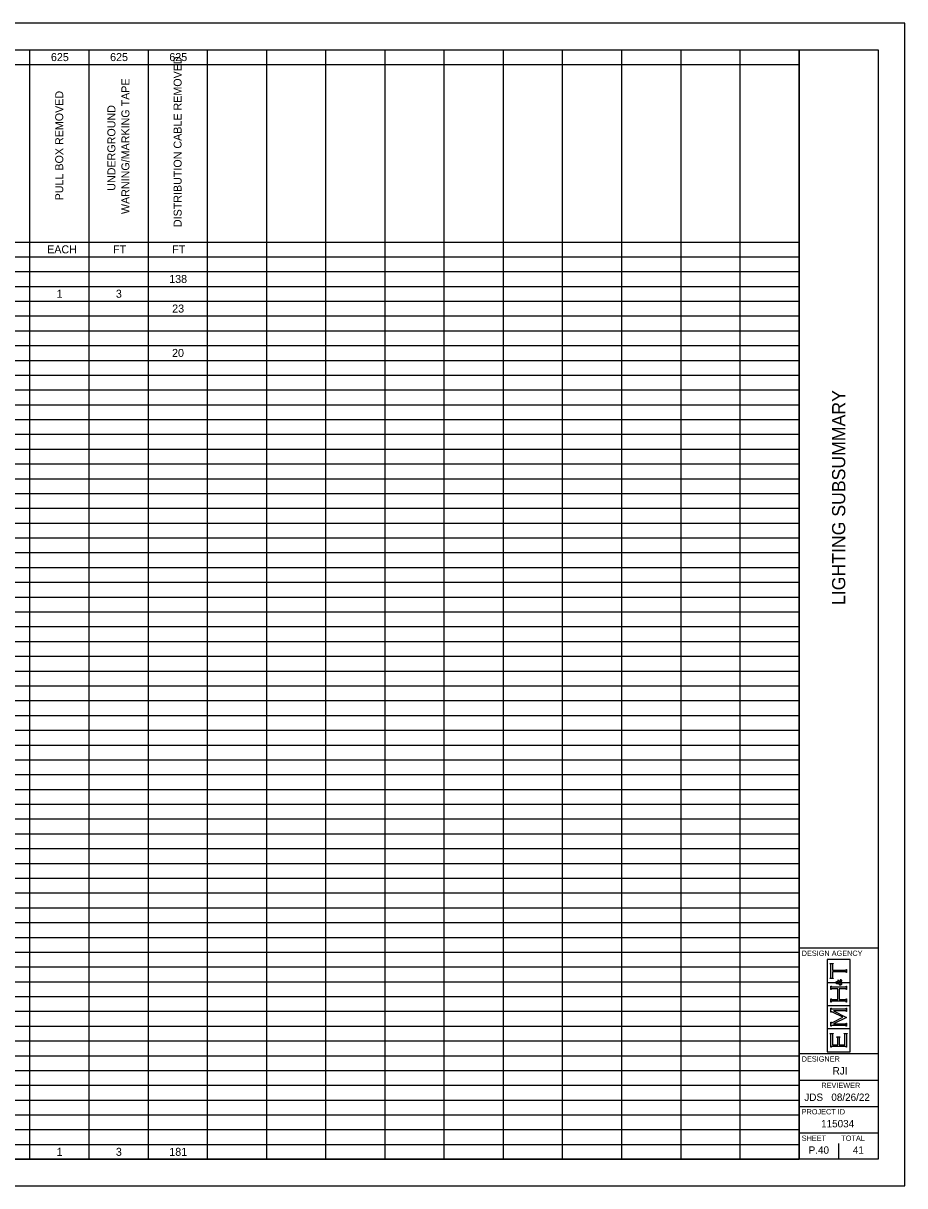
# Model space of a CAD drawing. Extents: x 0 to 34, y 0 to 22.
# Drawn here: x 17.32 to 34, y 0 to 22 of the extents above; entities that cross this region are included whole.
import ezdxf

# ---------------------------------------------------------------- set-up
doc = ezdxf.new("R2010")
doc.units = 0
for name, color, linetype in [('SH_Border', 7, 'Continuous'), ('SH_Cut_Line', 7, 'Continuous'), ('SH_Data', 7, 'Continuous'), ('SH_Text', 7, 'Continuous')]:
    doc.layers.add(name, color=color, linetype=linetype)

msp = doc.modelspace()

# ---------------------------------------------------------------- linework, layer by layer
at = {"layer": 'SH_Border'}
for p, q in [((32, 0.5), (32, 21.5)), ((32, 4.5), (33.5, 4.5)), ((32, 2.5), (33.5, 2.5)), ((32, 2), (33.5, 2)), ((32, 1.5), (33.5, 1.5)), ((32, 1), (33.5, 1))]:
    msp.add_line(p, q, dxfattribs=at)
msp.add_lwpolyline([(1.5, 21.5), (33.5, 21.5), (33.5, 0.5), (1.5, 0.5)], close=True, dxfattribs=at)
at = {"layer": 'SH_Cut_Line'}
msp.add_lwpolyline([(0, 0), (34, 0), (34, 22), (0, 22)], close=True, dxfattribs=at)
at = {"layer": 'SH_Data'}
for p, q in [((32.966, 4.28), (32.534, 4.28)), ((32.534, 4.28), (32.534, 3.848)), ((32.588, 4.199), (32.588, 4.206)), ((32.588, 4.206), (32.644, 4.206)), ((32.594, 4.198), (32.588, 4.199)), ((32.598, 4.196), (32.594, 4.198)), ((32.599, 4.194), (32.598, 4.196)), ((32.601, 4.191), (32.599, 4.194)), ((32.602, 4.187), (32.601, 4.191)), ((32.602, 4.181), (32.602, 4.187)), ((32.602, 3.947), (32.602, 4.181)), ((32.632, 4.191), (32.631, 4.187)), ((32.631, 4.187), (32.631, 4.181)), ((32.631, 4.181), (32.631, 4.081)), ((32.633, 4.194), (32.632, 4.191)), ((32.635, 4.196), (32.633, 4.194)), ((32.639, 4.198), (32.635, 4.196)), ((32.644, 4.199), (32.639, 4.198)), ((32.644, 4.206), (32.644, 4.199)), ((32.966, 3.848), (32.966, 4.28)), ((32.631, 4.081), (32.872, 4.081)), ((32.872, 4.047), (32.631, 4.047)), ((32.631, 4.047), (32.631, 3.947)), ((32.872, 4.081), (32.878, 4.081)), ((32.878, 4.047), (32.872, 4.047)), ((32.878, 4.081), (32.882, 4.082)), ((32.883, 4.046), (32.878, 4.047)), ((32.882, 4.082), (32.885, 4.084)), ((32.885, 4.044), (32.883, 4.046)), ((32.885, 4.084), (32.887, 4.085)), ((32.888, 4.042), (32.885, 4.044)), ((32.887, 4.085), (32.889, 4.089)), ((32.889, 4.039), (32.888, 4.042)), ((32.889, 4.089), (32.891, 4.095)), ((32.891, 4.033), (32.889, 4.039)), ((32.891, 4.095), (32.898, 4.095)), ((32.898, 4.033), (32.891, 4.033)), ((32.898, 4.095), (32.898, 4.033)), ((32.534, 3.848), (32.693, 3.848)), ((32.693, 3.842), (32.534, 3.842)), ((32.534, 3.842), (32.534, 3.41)), ((32.588, 3.928), (32.594, 3.93)), ((32.588, 3.921), (32.588, 3.928)), ((32.644, 3.921), (32.588, 3.921)), ((32.594, 3.93), (32.598, 3.932)), ((32.598, 3.932), (32.599, 3.934)), ((32.599, 3.934), (32.601, 3.937)), ((32.601, 3.937), (32.602, 3.941)), ((32.602, 3.941), (32.602, 3.947)), ((32.602, 3.714), (32.602, 3.776)), ((32.602, 3.776), (32.609, 3.776)), ((32.609, 3.776), (32.611, 3.77)), ((32.611, 3.77), (32.612, 3.766)), ((32.612, 3.766), (32.615, 3.765)), ((32.615, 3.765), (32.617, 3.763)), ((32.617, 3.763), (32.622, 3.762)), ((32.622, 3.762), (32.628, 3.762)), ((32.628, 3.762), (32.872, 3.762)), ((32.631, 3.947), (32.631, 3.941)), ((32.631, 3.941), (32.632, 3.937)), ((32.632, 3.937), (32.633, 3.934)), ((32.633, 3.934), (32.635, 3.932)), ((32.635, 3.932), (32.639, 3.93)), ((32.639, 3.93), (32.644, 3.928)), ((32.644, 3.928), (32.644, 3.921)), ((32.693, 3.848), (32.693, 3.842)), ((32.701, 3.852), (32.703, 3.857)), ((32.701, 3.846), (32.701, 3.852)), ((32.701, 3.84), (32.701, 3.846)), ((32.703, 3.835), (32.701, 3.84)), ((32.703, 3.857), (32.706, 3.861)), ((32.706, 3.83), (32.703, 3.835)), ((32.706, 3.861), (32.71, 3.864)), ((32.707, 3.852), (32.706, 3.849)), ((32.706, 3.849), (32.706, 3.846)), ((32.706, 3.846), (32.706, 3.842)), ((32.706, 3.842), (32.708, 3.839)), ((32.71, 3.824), (32.706, 3.83)), ((32.71, 3.854), (32.707, 3.852)), ((32.708, 3.839), (32.711, 3.837)), ((32.71, 3.864), (32.714, 3.866)), ((32.712, 3.856), (32.71, 3.854)), ((32.717, 3.821), (32.71, 3.824)), ((32.711, 3.837), (32.714, 3.835)), ((32.715, 3.857), (32.712, 3.856)), ((32.714, 3.866), (32.719, 3.866)), ((32.714, 3.835), (32.716, 3.834)), ((32.718, 3.857), (32.715, 3.857)), ((32.716, 3.834), (32.719, 3.834)), ((32.725, 3.821), (32.717, 3.821)), ((32.723, 3.857), (32.718, 3.857)), ((32.719, 3.866), (32.724, 3.866)), ((32.719, 3.834), (32.722, 3.834)), ((32.722, 3.834), (32.724, 3.834)), ((32.727, 3.856), (32.723, 3.857)), ((32.724, 3.866), (32.728, 3.864)), ((32.724, 3.834), (32.727, 3.835)), ((32.728, 3.821), (32.725, 3.821)), ((32.73, 3.853), (32.727, 3.856)), ((32.727, 3.835), (32.73, 3.836)), ((32.728, 3.864), (32.732, 3.861)), ((32.731, 3.822), (32.728, 3.821)), ((32.734, 3.85), (32.73, 3.853)), ((32.73, 3.836), (32.734, 3.837)), ((32.734, 3.822), (32.731, 3.822)), ((32.732, 3.861), (32.736, 3.857)), ((32.737, 3.845), (32.734, 3.85)), ((32.734, 3.837), (32.74, 3.839)), ((32.737, 3.823), (32.734, 3.822)), ((32.736, 3.857), (32.74, 3.851)), ((32.74, 3.839), (32.737, 3.845)), ((32.741, 3.825), (32.737, 3.823)), ((32.738, 3.867), (32.738, 3.898)), ((32.738, 3.898), (32.741, 3.898)), ((32.741, 3.867), (32.738, 3.867)), ((32.74, 3.851), (32.745, 3.842)), ((32.741, 3.898), (32.741, 3.894)), ((32.741, 3.894), (32.742, 3.891)), ((32.742, 3.871), (32.741, 3.869)), ((32.741, 3.869), (32.741, 3.867)), ((32.746, 3.827), (32.741, 3.825)), ((32.742, 3.891), (32.744, 3.889)), ((32.743, 3.872), (32.742, 3.871)), ((32.745, 3.873), (32.743, 3.872)), ((32.744, 3.889), (32.745, 3.887)), ((32.745, 3.887), (32.75, 3.883)), ((32.747, 3.874), (32.745, 3.873)), ((32.745, 3.842), (32.755, 3.848)), ((32.753, 3.815), (32.746, 3.827)), ((32.749, 3.874), (32.747, 3.874)), ((32.756, 3.874), (32.749, 3.874)), ((32.75, 3.883), (32.757, 3.879)), ((32.757, 3.832), (32.751, 3.829)), ((32.751, 3.829), (32.755, 3.824)), ((32.759, 3.808), (32.753, 3.815)), ((32.755, 3.848), (32.765, 3.855)), ((32.755, 3.824), (32.758, 3.819)), ((32.764, 3.87), (32.756, 3.874)), ((32.757, 3.879), (32.765, 3.875)), ((32.762, 3.835), (32.757, 3.832)), ((32.758, 3.819), (32.762, 3.817)), ((32.765, 3.803), (32.759, 3.808)), ((32.766, 3.838), (32.762, 3.835)), ((32.762, 3.817), (32.766, 3.814)), ((32.775, 3.861), (32.764, 3.87)), ((32.765, 3.875), (32.772, 3.87)), ((32.765, 3.855), (32.775, 3.861)), ((32.77, 3.799), (32.765, 3.803)), ((32.77, 3.84), (32.766, 3.838)), ((32.766, 3.814), (32.771, 3.812)), ((32.776, 3.845), (32.77, 3.84)), ((32.776, 3.797), (32.77, 3.799)), ((32.771, 3.812), (32.775, 3.812)), ((32.772, 3.87), (32.779, 3.865)), ((32.775, 3.812), (32.78, 3.812)), ((32.785, 3.851), (32.776, 3.845)), ((32.782, 3.797), (32.776, 3.797)), ((32.779, 3.865), (32.784, 3.869)), ((32.78, 3.812), (32.785, 3.814)), ((32.781, 3.9), (32.783, 3.902)), ((32.785, 3.899), (32.781, 3.9)), ((32.788, 3.797), (32.782, 3.797)), ((32.783, 3.902), (32.79, 3.901)), ((32.784, 3.869), (32.787, 3.873)), ((32.788, 3.897), (32.785, 3.899)), ((32.789, 3.846), (32.785, 3.851)), ((32.785, 3.814), (32.789, 3.817)), ((32.787, 3.873), (32.789, 3.876)), ((32.789, 3.895), (32.788, 3.897)), ((32.793, 3.8), (32.788, 3.797)), ((32.791, 3.892), (32.789, 3.895)), ((32.789, 3.876), (32.791, 3.88)), ((32.794, 3.859), (32.789, 3.855)), ((32.789, 3.855), (32.795, 3.849)), ((32.792, 3.842), (32.789, 3.846)), ((32.789, 3.817), (32.793, 3.821)), ((32.79, 3.901), (32.795, 3.898)), ((32.792, 3.89), (32.791, 3.892)), ((32.791, 3.88), (32.792, 3.883)), ((32.792, 3.886), (32.792, 3.89)), ((32.792, 3.883), (32.792, 3.886)), ((32.793, 3.839), (32.792, 3.842)), ((32.794, 3.837), (32.793, 3.839)), ((32.793, 3.821), (32.795, 3.825)), ((32.797, 3.804), (32.793, 3.8)), ((32.798, 3.864), (32.794, 3.859)), ((32.795, 3.834), (32.794, 3.837)), ((32.795, 3.898), (32.799, 3.894)), ((32.795, 3.849), (32.798, 3.843)), ((32.795, 3.831), (32.795, 3.834)), ((32.795, 3.825), (32.795, 3.831)), ((32.801, 3.809), (32.797, 3.804)), ((32.8, 3.868), (32.798, 3.864)), ((32.798, 3.843), (32.8, 3.839)), ((32.799, 3.894), (32.802, 3.89)), ((32.802, 3.872), (32.8, 3.868)), ((32.8, 3.839), (32.802, 3.834)), ((32.803, 3.815), (32.801, 3.809)), ((32.802, 3.89), (32.803, 3.885)), ((32.803, 3.876), (32.802, 3.872)), ((32.802, 3.834), (32.803, 3.829)), ((32.803, 3.885), (32.803, 3.88)), ((32.803, 3.88), (32.803, 3.876)), ((32.807, 3.842), (32.803, 3.848)), ((32.803, 3.848), (32.966, 3.848)), ((32.803, 3.829), (32.803, 3.823)), ((32.803, 3.823), (32.803, 3.815)), ((32.966, 3.842), (32.807, 3.842)), ((32.872, 3.762), (32.878, 3.762)), ((32.878, 3.762), (32.882, 3.763)), ((32.882, 3.763), (32.885, 3.765)), ((32.885, 3.765), (32.887, 3.766)), ((32.887, 3.766), (32.889, 3.77)), ((32.889, 3.77), (32.891, 3.776)), ((32.891, 3.776), (32.898, 3.776)), ((32.898, 3.776), (32.898, 3.714)), ((32.966, 3.41), (32.966, 3.842)), ((32.609, 3.714), (32.602, 3.714)), ((32.602, 3.477), (32.602, 3.538)), ((32.602, 3.538), (32.609, 3.538)), ((32.61, 3.72), (32.609, 3.714)), ((32.609, 3.538), (32.611, 3.533)), ((32.612, 3.723), (32.61, 3.72)), ((32.611, 3.533), (32.612, 3.529)), ((32.615, 3.725), (32.612, 3.723)), ((32.612, 3.529), (32.615, 3.527)), ((32.617, 3.727), (32.615, 3.725)), ((32.615, 3.527), (32.617, 3.526)), ((32.622, 3.728), (32.617, 3.727)), ((32.617, 3.526), (32.622, 3.525)), ((32.628, 3.728), (32.622, 3.728)), ((32.622, 3.525), (32.628, 3.525)), ((32.732, 3.728), (32.628, 3.728)), ((32.628, 3.525), (32.732, 3.525)), ((32.732, 3.525), (32.732, 3.728)), ((32.872, 3.728), (32.76, 3.728)), ((32.76, 3.728), (32.76, 3.525)), ((32.76, 3.525), (32.872, 3.525)), ((32.878, 3.728), (32.872, 3.728)), ((32.872, 3.525), (32.878, 3.525)), ((32.883, 3.727), (32.878, 3.728)), ((32.878, 3.525), (32.883, 3.525)), ((32.885, 3.725), (32.883, 3.727)), ((32.883, 3.525), (32.885, 3.527)), ((32.888, 3.723), (32.885, 3.725)), ((32.885, 3.527), (32.888, 3.529)), ((32.889, 3.72), (32.888, 3.723)), ((32.888, 3.529), (32.889, 3.533)), ((32.891, 3.714), (32.889, 3.72)), ((32.889, 3.533), (32.891, 3.538)), ((32.898, 3.714), (32.891, 3.714)), ((32.891, 3.538), (32.898, 3.538)), ((32.898, 3.538), (32.898, 3.477)), ((32.534, 3.41), (32.966, 3.41)), ((32.966, 3.405), (32.534, 3.405)), ((32.534, 3.405), (32.534, 2.973)), ((32.609, 3.477), (32.602, 3.477)), ((32.602, 3.283), (32.602, 3.36)), ((32.602, 3.36), (32.609, 3.36)), ((32.61, 3.482), (32.609, 3.477)), ((32.609, 3.36), (32.611, 3.354)), ((32.612, 3.486), (32.61, 3.482)), ((32.611, 3.354), (32.612, 3.351)), ((32.615, 3.488), (32.612, 3.486)), ((32.612, 3.351), (32.615, 3.349)), ((32.617, 3.49), (32.615, 3.488)), ((32.615, 3.349), (32.617, 3.347)), ((32.622, 3.491), (32.617, 3.49)), ((32.617, 3.347), (32.622, 3.346)), ((32.628, 3.491), (32.622, 3.491)), ((32.622, 3.346), (32.628, 3.346)), ((32.872, 3.491), (32.628, 3.491)), ((32.628, 3.346), (32.872, 3.346)), ((32.872, 3.312), (32.649, 3.312)), ((32.649, 3.312), (32.898, 3.186)), ((32.75, 3.5), (32.75, 3.5)), ((32.878, 3.491), (32.872, 3.491)), ((32.872, 3.346), (32.878, 3.346)), ((32.878, 3.312), (32.872, 3.312)), ((32.883, 3.49), (32.878, 3.491)), ((32.878, 3.346), (32.882, 3.347)), ((32.883, 3.311), (32.878, 3.312)), ((32.882, 3.347), (32.885, 3.349)), ((32.885, 3.488), (32.883, 3.49)), ((32.885, 3.31), (32.883, 3.311)), ((32.887, 3.486), (32.885, 3.488)), ((32.885, 3.349), (32.887, 3.351)), ((32.887, 3.308), (32.885, 3.31)), ((32.887, 3.351), (32.889, 3.354)), ((32.889, 3.304), (32.887, 3.308)), ((32.889, 3.482), (32.887, 3.486)), ((32.891, 3.477), (32.889, 3.482)), ((32.889, 3.354), (32.891, 3.36)), ((32.891, 3.298), (32.889, 3.304)), ((32.898, 3.477), (32.891, 3.477)), ((32.891, 3.36), (32.898, 3.36)), ((32.898, 3.36), (32.898, 3.298)), ((32.966, 2.973), (32.966, 3.405)), ((32.609, 3.283), (32.602, 3.283)), ((32.602, 3.017), (32.602, 3.094)), ((32.602, 3.094), (32.609, 3.094)), ((32.612, 3.29), (32.609, 3.283)), ((32.609, 3.094), (32.612, 3.087)), ((32.615, 3.293), (32.612, 3.29)), ((32.612, 3.087), (32.615, 3.083)), ((32.618, 3.293), (32.615, 3.293)), ((32.615, 3.083), (32.618, 3.083)), ((32.621, 3.293), (32.618, 3.293)), ((32.618, 3.083), (32.62, 3.083)), ((32.62, 3.083), (32.625, 3.086)), ((32.626, 3.292), (32.621, 3.293)), ((32.625, 3.086), (32.635, 3.09)), ((32.633, 3.288), (32.626, 3.292)), ((32.831, 3.189), (32.633, 3.288)), ((32.635, 3.09), (32.831, 3.189)), ((32.898, 3.186), (32.649, 3.062)), ((32.898, 3.298), (32.891, 3.298)), ((32.534, 2.973), (32.966, 2.973)), ((32.966, 2.967), (32.534, 2.967)), ((32.534, 2.967), (32.534, 2.535)), ((32.588, 2.874), (32.588, 2.881)), ((32.588, 2.881), (32.644, 2.881)), ((32.594, 2.873), (32.588, 2.874)), ((32.598, 2.871), (32.594, 2.873)), ((32.599, 2.868), (32.598, 2.871)), ((32.601, 2.866), (32.599, 2.868)), ((32.602, 2.862), (32.601, 2.866)), ((32.609, 3.017), (32.602, 3.017)), ((32.602, 2.856), (32.602, 2.862)), ((32.61, 3.023), (32.609, 3.017)), ((32.612, 3.026), (32.61, 3.023)), ((32.615, 3.028), (32.612, 3.026)), ((32.617, 3.03), (32.615, 3.028)), ((32.622, 3.031), (32.617, 3.03)), ((32.628, 3.031), (32.622, 3.031)), ((32.872, 3.031), (32.628, 3.031)), ((32.632, 2.866), (32.631, 2.862)), ((32.631, 2.862), (32.631, 2.856)), ((32.633, 2.868), (32.632, 2.866)), ((32.635, 2.871), (32.633, 2.868)), ((32.639, 2.873), (32.635, 2.871)), ((32.644, 2.874), (32.639, 2.873)), ((32.644, 2.881), (32.644, 2.874)), ((32.649, 3.062), (32.872, 3.062)), ((32.855, 2.877), (32.855, 2.884)), ((32.855, 2.884), (32.912, 2.884)), ((32.861, 2.876), (32.855, 2.877)), ((32.865, 2.874), (32.861, 2.876)), ((32.867, 2.872), (32.865, 2.874)), ((32.868, 2.869), (32.867, 2.872)), ((32.869, 2.865), (32.868, 2.869)), ((32.869, 2.859), (32.869, 2.865)), ((32.872, 3.062), (32.878, 3.062)), ((32.878, 3.031), (32.872, 3.031)), ((32.878, 3.062), (32.882, 3.063)), ((32.883, 3.03), (32.878, 3.031)), ((32.882, 3.063), (32.885, 3.065)), ((32.885, 3.028), (32.883, 3.03)), ((32.885, 3.065), (32.887, 3.067)), ((32.887, 3.026), (32.885, 3.028)), ((32.887, 3.067), (32.889, 3.07)), ((32.889, 3.023), (32.887, 3.026)), ((32.889, 3.07), (32.891, 3.076)), ((32.891, 3.017), (32.889, 3.023)), ((32.891, 3.076), (32.898, 3.076)), ((32.898, 3.017), (32.891, 3.017)), ((32.898, 3.076), (32.898, 3.017)), ((32.899, 2.869), (32.898, 2.865)), ((32.898, 2.865), (32.898, 2.858)), ((32.901, 2.871), (32.899, 2.869)), ((32.903, 2.874), (32.901, 2.871)), ((32.906, 2.876), (32.903, 2.874)), ((32.912, 2.877), (32.906, 2.876)), ((32.912, 2.884), (32.912, 2.877)), ((32.966, 2.535), (32.966, 2.967)), ((32.602, 2.621), (32.602, 2.856)), ((32.631, 2.856), (32.631, 2.669)), ((32.631, 2.669), (32.732, 2.669)), ((32.718, 2.81), (32.718, 2.816)), ((32.718, 2.816), (32.774, 2.816)), ((32.723, 2.808), (32.718, 2.81)), ((32.727, 2.806), (32.723, 2.808)), ((32.729, 2.804), (32.727, 2.806)), ((32.731, 2.801), (32.729, 2.804)), ((32.732, 2.797), (32.731, 2.801)), ((32.732, 2.791), (32.732, 2.797)), ((32.732, 2.669), (32.732, 2.791)), ((32.761, 2.801), (32.76, 2.797)), ((32.76, 2.797), (32.76, 2.791)), ((32.76, 2.791), (32.76, 2.669)), ((32.76, 2.669), (32.869, 2.669)), ((32.763, 2.804), (32.761, 2.801)), ((32.765, 2.806), (32.763, 2.804)), ((32.768, 2.808), (32.765, 2.806)), ((32.774, 2.81), (32.768, 2.808)), ((32.774, 2.816), (32.774, 2.81)), ((32.869, 2.669), (32.869, 2.859)), ((32.898, 2.858), (32.898, 2.621)), ((32.534, 2.535), (32.966, 2.535)), ((32.609, 2.621), (32.602, 2.621)), ((32.611, 2.626), (32.609, 2.621)), ((32.612, 2.63), (32.611, 2.626)), ((32.615, 2.632), (32.612, 2.63)), ((32.617, 2.634), (32.615, 2.632)), ((32.622, 2.635), (32.617, 2.634)), ((32.628, 2.635), (32.622, 2.635)), ((32.872, 2.635), (32.628, 2.635)), ((32.878, 2.635), (32.872, 2.635)), ((32.883, 2.634), (32.878, 2.635)), ((32.885, 2.632), (32.883, 2.634)), ((32.887, 2.63), (32.885, 2.632)), ((32.889, 2.627), (32.887, 2.63)), ((32.891, 2.621), (32.889, 2.627)), ((32.898, 2.621), (32.891, 2.621)), ((32.375, 0.675), (32.375, 0.675)), ((32.75, 0.5), (32.75, 0.8))]:
    msp.add_line(p, q, dxfattribs=at)
at = {"layer": 'SH_Text'}
for p, q in [((1.5, 21.5), (32.001, 21.5)), ((17.442, 21.5), (17.442, 0.502)), ((18.562, 21.5), (18.562, 0.502)), ((19.682, 21.5), (19.682, 0.502)), ((20.802, 21.5), (20.802, 0.502)), ((21.922, 21.5), (21.922, 0.502)), ((23.042, 21.5), (23.042, 0.502)), ((24.162, 21.5), (24.162, 0.502)), ((25.282, 21.5), (25.282, 0.502)), ((26.402, 21.5), (26.402, 0.502)), ((27.521, 21.5), (27.521, 0.502)), ((28.641, 21.5), (28.641, 0.502)), ((29.761, 21.5), (29.761, 0.502)), ((30.881, 21.5), (30.881, 0.502)), ((32.001, 21.5), (32.001, 0.502)), ((10.723, 21.22), (32.001, 21.22)), ((10.723, 17.86), (32.001, 17.86)), ((1.5, 17.58), (32.001, 17.58)), ((1.5, 17.3), (32.001, 17.3)), ((1.5, 17.02), (32.001, 17.02)), ((1.5, 16.74), (32.001, 16.74)), ((1.5, 16.46), (32.001, 16.46)), ((1.5, 16.18), (32.001, 16.18)), ((1.5, 15.9), (32.001, 15.9)), ((1.5, 15.62), (32.001, 15.62)), ((1.5, 15.34), (32.001, 15.34)), ((1.5, 15.061), (32.001, 15.061)), ((1.5, 14.781), (32.001, 14.781)), ((1.5, 14.501), (32.001, 14.501)), ((1.5, 14.221), (32.001, 14.221)), ((1.5, 13.941), (32.001, 13.941)), ((1.5, 13.661), (32.001, 13.661)), ((1.5, 13.381), (32.001, 13.381)), ((1.5, 13.101), (32.001, 13.101)), ((1.5, 12.821), (32.001, 12.821)), ((1.5, 12.541), (32.001, 12.541)), ((1.5, 12.261), (32.001, 12.261)), ((1.5, 11.981), (32.001, 11.981)), ((1.5, 11.701), (32.001, 11.701)), ((1.5, 11.421), (32.001, 11.421)), ((1.5, 11.141), (32.001, 11.141)), ((1.5, 10.861), (32.001, 10.861)), ((1.5, 10.581), (32.001, 10.581)), ((1.5, 10.301), (32.001, 10.301)), ((1.5, 10.021), (32.001, 10.021)), ((1.5, 9.741), (32.001, 9.741)), ((1.5, 9.461), (32.001, 9.461)), ((1.5, 9.181), (32.001, 9.181)), ((1.5, 8.901), (32.001, 8.901)), ((1.5, 8.621), (32.001, 8.621)), ((1.5, 8.341), (32.001, 8.341)), ((1.5, 8.061), (32.001, 8.061)), ((1.5, 7.781), (32.001, 7.781)), ((1.5, 7.501), (32.001, 7.501)), ((1.5, 7.221), (32.001, 7.221)), ((1.5, 6.941), (32.001, 6.941)), ((1.5, 6.661), (32.001, 6.661)), ((1.5, 6.381), (32.001, 6.381)), ((1.5, 6.101), (32.001, 6.101)), ((1.5, 5.821), (32.001, 5.821)), ((1.5, 5.541), (32.001, 5.541)), ((1.5, 5.261), (32.001, 5.261)), ((1.5, 4.981), (32.001, 4.981)), ((1.5, 4.701), (32.001, 4.701)), ((1.5, 4.421), (32.001, 4.421)), ((1.5, 4.141), (32.001, 4.141)), ((1.5, 3.861), (32.001, 3.861)), ((1.5, 3.581), (32.001, 3.581)), ((1.5, 3.301), (32.001, 3.301)), ((1.5, 3.021), (32.001, 3.021)), ((1.5, 2.741), (32.001, 2.741)), ((1.5, 2.461), (32.001, 2.461)), ((1.5, 2.182), (32.001, 2.182)), ((1.5, 1.902), (32.001, 1.902)), ((1.5, 1.622), (32.001, 1.622)), ((1.5, 1.342), (32.001, 1.342)), ((1.5, 1.062), (32.001, 1.062)), ((1.5, 0.782), (32.001, 0.782)), ((1.5, 0.502), (32.001, 0.502))]:
    msp.add_line(p, q, dxfattribs=at)

# ---------------------------------------------------------------- texts
at = {"layer": 'SH_Data'}
msp.add_text('LIGHTING SUBSUMMARY', height=0.25, rotation=90, dxfattribs=at).set_placement((32.875, 10.99))
for s, height, p in [('DESIGN AGENCY', 0.1, (32.05, 4.35)), ('DESIGNER', 0.1, (32.05, 2.35)), ('RJI', 0.14, (32.636, 2.105)), ('REVIEWER', 0.1, (32.422, 1.85)), ('JDS', 0.14, (32.1, 1.605)), ('08/26/22', 0.14, (32.611, 1.605)), ('PROJECT ID', 0.1, (32.05, 1.35)), ('115034', 0.14, (32.418, 1.105)), ('SHEET', 0.1, (32.05, 0.85)), ('TOTAL', 0.1, (32.8, 0.85)), ('P.40', 0.14, (32.182, 0.605)), ('41', 0.14, (33.019, 0.605))]:
    msp.add_text(s, height=height, dxfattribs=at).set_placement(p)
at = {"layer": 'SH_Text'}
for s, height, p in [('625', 0.1515, (17.845, 21.284)), ('625', 0.1515, (18.965, 21.284)), ('625', 0.1515, (20.085, 21.284)), ('EACH', 0.1515, (17.774, 17.645)), ('FT', 0.1515, (19.021, 17.645)), ('FT', 0.1515, (20.141, 17.645)), ('138', 0.1515, (20.083, 17.085)), ('1', 0.152, (17.954, 16.805)), ('3', 0.152, (19.074, 16.805)), ('23', 0.1515, (20.14, 16.525)), ('20', 0.1515, (20.137, 15.685)), ('1', 0.152, (17.954, 0.566)), ('3', 0.152, (19.074, 0.566)), ('181', 0.1515, (20.085, 0.566))]:
    msp.add_text(s, height=height, dxfattribs=at).set_placement(p)
for s, p in [('DISTRIBUTION CABLE REMOVED', (20.318, 18.142)), ('WARNING/MARKING TAPE', (19.33, 18.389)), ('PULL BOX REMOVED', (18.078, 18.648)), ('UNDERGROUND ', (19.065, 18.83))]:
    msp.add_text(s, height=0.15152, rotation=90, dxfattribs=at).set_placement(p)

doc.saveas('drawing.dxf')
